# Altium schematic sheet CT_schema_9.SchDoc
size 274 x 160 mm
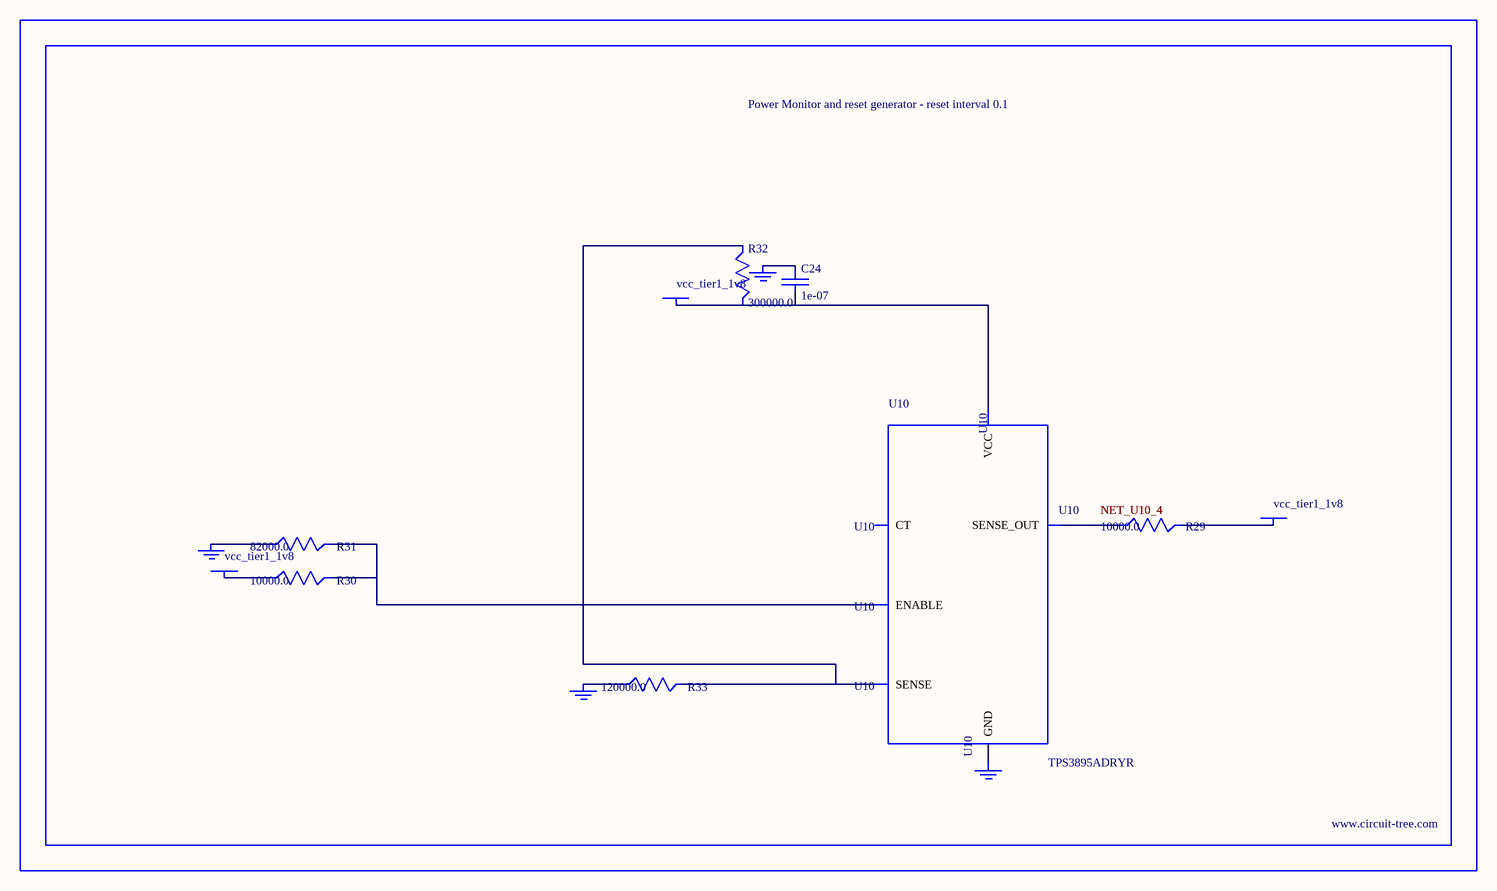
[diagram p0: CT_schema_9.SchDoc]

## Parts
BORDER8  (no value)
C24  1e-07  [C0402]
GND_INSTANCE_8_0  (no value)
GND_INSTANCE_8_1  (no value)
GND_INSTANCE_8_2  (no value)
GND_INSTANCE_8_3  (no value)
POWER_INSTANCE_8_0  vcc_tier1_1v8
POWER_INSTANCE_8_1  vcc_tier1_1v8
POWER_INSTANCE_8_2  vcc_tier1_1v8
R29  10000.0  [R0603]
R30  10000.0  [R0603]
R31  82000.0  [R0603]
R32  300000.0  [R0603]
R33  120000.0  [R0603]
U10  TPS3895ADRYR  [SON-6]

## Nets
NetC24_1: C24.1 GND_INSTANCE_8_2.0(GND)
NetC24_2: C24.2 POWER_INSTANCE_8_2.0(PWR) R32.2 U10.6(VCC)
NetGND_INSTANCE_8_0_0: GND_INSTANCE_8_0.0(GND) R31.1
NetGND_INSTANCE_8_1_0: GND_INSTANCE_8_1.0(GND) R33.1
NetGND_INSTANCE_8_3_0: GND_INSTANCE_8_3.0(GND) U10.2(GND)
NetPOWER_INSTANCE_8_0_0: POWER_INSTANCE_8_0.0(PWR) R30.1
NetPOWER_INSTANCE_8_1_0: POWER_INSTANCE_8_1.0(PWR) R29.2
NetR29_1: R29.1 U10.4(SENSE_OUT)
NetR30_2: R30.2 R31.2 U10.1(ENABLE)
NetR32_1: R32.1 R33.2 U10.3(SENSE)

Not connected (* = marked no-connect by the designer): U10 5(CT)

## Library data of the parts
BORDER8 = BORDER_PAGE8
C24 = C0402C104K3RACTU
GND_INSTANCE_8_0-GND_INSTANCE_8_3 = GND
POWER_INSTANCE_8_0-POWER_INSTANCE_8_2 = PWR
R29 R30 = RC0603JR-0710KL
R31 = RC0603JR-0782KL
R32 = RC0603JR-07300KL
R33 = RC0603JR-07120KL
